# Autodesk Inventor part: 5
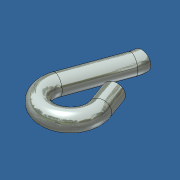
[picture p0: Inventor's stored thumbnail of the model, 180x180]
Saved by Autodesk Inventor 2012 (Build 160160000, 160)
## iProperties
Created: 2013-04
Part Number: 5
Material: Steel
Document SubType Name: Modeling
Designer: Admin
Density: 7.85 g/cm^3
Mass: 3.82737 g
Surface Area: 5.12697 cm^2
Volume: 0.487564 cm^3
Author: Admin
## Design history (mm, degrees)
node "51"
node "5"
node "Base1"
